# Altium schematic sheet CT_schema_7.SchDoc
size 278 x 170 mm
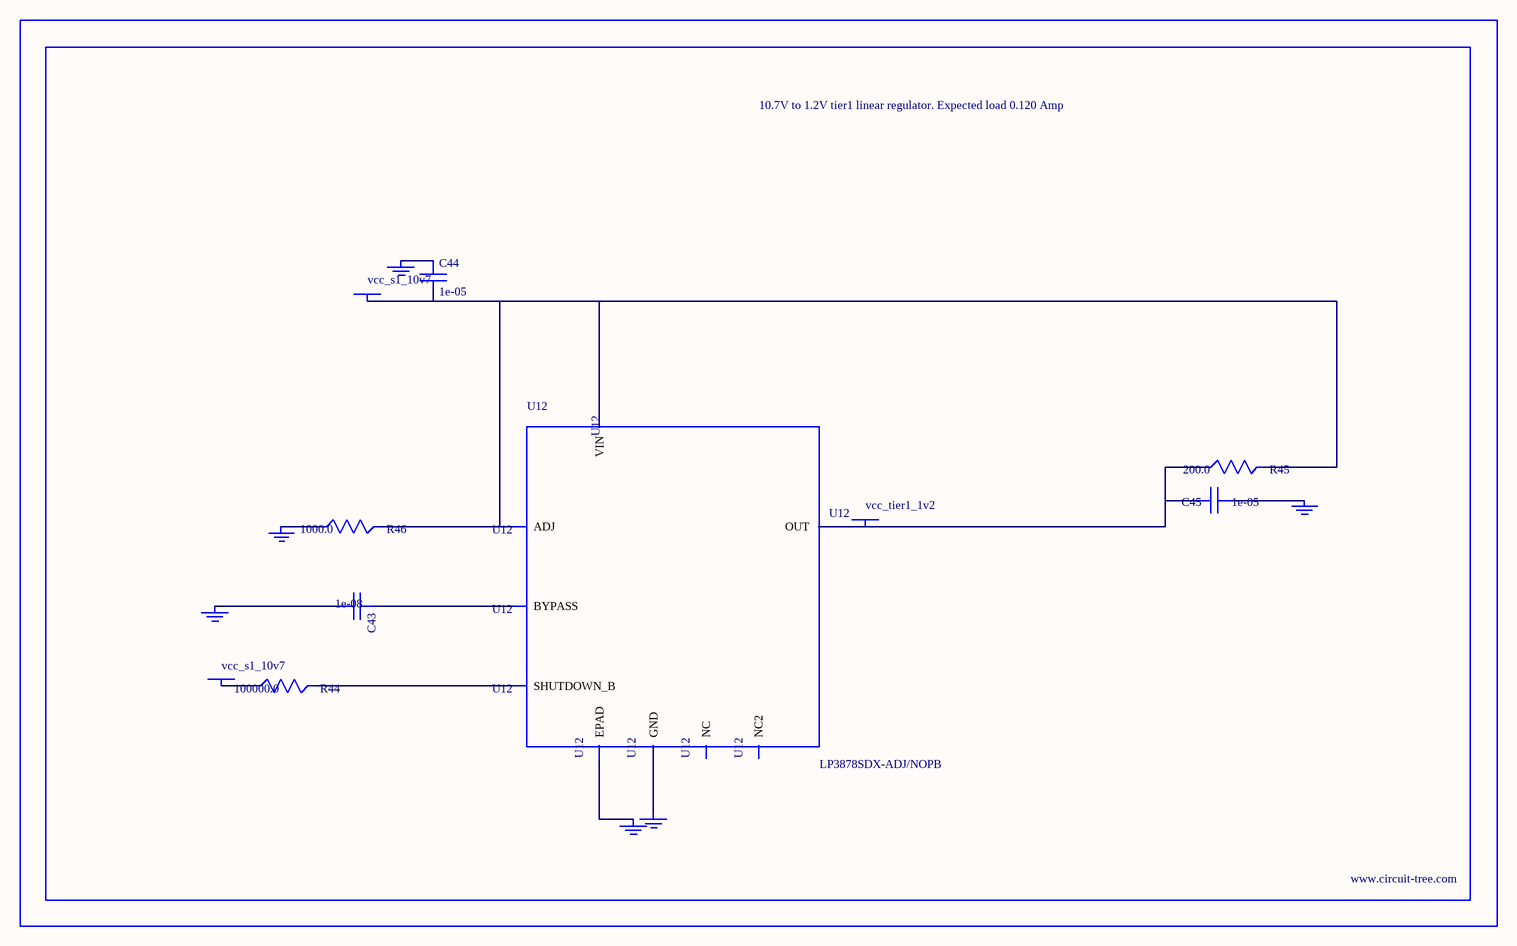
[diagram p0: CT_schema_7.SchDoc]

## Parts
BORDER6  (no value)
C43  1e-08  [C0402]
C44  1e-05  [C1206]
C45  1e-05  [C0805]
GND_INSTANCE_6_0  (no value)
GND_INSTANCE_6_1  (no value)
GND_INSTANCE_6_2  (no value)
GND_INSTANCE_6_3  (no value)
GND_INSTANCE_6_4  (no value)
GND_INSTANCE_6_5  (no value)
POWER_INSTANCE_6_0  vcc_s1_10v7
POWER_INSTANCE_6_1  vcc_s1_10v7
POWER_INSTANCE_6_2  vcc_tier1_1v2
R44  100000.0  [R0603]
R45  200.0  [R0603]
R46  1000.0  [R0603]
U12  LP3878SDX-ADJ/NOPB  [WSON-8]

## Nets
NetC43_1: C43.1 U12.1(BYPASS)
NetC43_2: C43.2 GND_INSTANCE_6_0.0(GND)
NetC44_1: C44.1 GND_INSTANCE_6_1.0(GND)
NetC44_2: C44.2 POWER_INSTANCE_6_0.0(PWR) R45.2 R46.2 U12.4(VIN) U12.6(ADJ)
NetC45_1: C45.1 GND_INSTANCE_6_2.0(GND)
NetC45_2: C45.2 POWER_INSTANCE_6_2.0(PWR) R45.1 U12.5(OUT)
NetGND_INSTANCE_6_3_0: GND_INSTANCE_6_3.0(GND) R46.1
NetGND_INSTANCE_6_4_0: GND_INSTANCE_6_4.0(GND) U12.PAD(EPAD)
NetGND_INSTANCE_6_5_0: GND_INSTANCE_6_5.0(GND) U12.3(GND)
NetPOWER_INSTANCE_6_1_0: POWER_INSTANCE_6_1.0(PWR) R44.1
NetR44_2: R44.2 U12.8(SHUTDOWN_B)

Not connected (* = marked no-connect by the designer): U12 2(NC) 7(NC2)

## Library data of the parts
BORDER6 = BORDER_PAGE6
C43 = C0402C103K3RAC
C44 = C1206C106K3RACTU
C45 = GRM219R60J106ME19D
GND_INSTANCE_6_0-GND_INSTANCE_6_5 = GND
POWER_INSTANCE_6_0-POWER_INSTANCE_6_2 = PWR
R44 = RC0603JR-07100KL
R45 = RC0603JR-07200RL
R46 = RC0603JR-071KL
